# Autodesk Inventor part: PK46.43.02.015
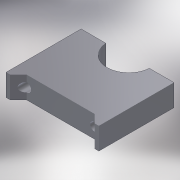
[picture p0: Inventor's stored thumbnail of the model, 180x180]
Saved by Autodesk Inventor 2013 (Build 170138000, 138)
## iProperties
Shininess: 64.0
Length Units: 11269
Angle Units: 11279
Time Units: 11290
Mass Units: 11283
Length Display Precision: 3
Angle Display Precision: 2
Compacted: True
Part Number: PK46.43.02.015
Document SubType Name: Modeling
Created: 2004-12
Material: Сталь высокопрочная низколегированная
Designer: ELarisa
Manufacturer: Standard
Standards Organization: Custom
Density: 7.84 g/cm^3
Density: 0.0
Volumn: 0.0
Area: 0.0
PropertySet Name: Model Information
Control State: 0
Master: False
Checked Out: False
Checked Out Date: 2008-10-09
Last Check In Date: 2008-10-09
Author: ELarisa
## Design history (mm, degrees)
sketch "Эскиз1"
  geometry: L1 (-26.065, -28.063)-(-26.065, 26.937); L2 (41.935, 26.937)-(41.935, -28.063); L3 (7.935, 36.963)-(7.935, -16.079); L4 (41.935, -28.063)-(38.935, -28.063); L5 (-23.065, -28.063)-(-26.065, -28.063); L6 (-26.065, 26.937)-(-8.034, 26.937); L7 (23.904, 26.937)-(41.935, 26.937); L8 (-23.065, -28.063)-(-17.065, -22.063); L9 (-17.065, -22.063)-(32.935, -22.063); L10 (32.935, -22.063)-(38.935, -28.063); A1 r 16 centre (7.935, 27.937) between (-8.034, 26.937) and (23.904, 26.937)
  constraints: 20 end point, 6 parallel, 5 perpendicular, 2 point on circle, 1 centre point, 1 collinear, 1 point on line, 1 vertical, 1 other
  dimensions: "d0" = 55 distance of L1.start L1.end; "d1" = 68 distance of L1.end L2.start; "d2" = 34 distance from line of L1 A1.centre; "d6" = 32 diameter of A1; "d20" = 1 distance from line of L7 A1.centre; "d21" = 55 distance of L2.start L2.end (= d0); "d23" = 6 distance between parallel lines of L9 L5; "d24" = 50 distance of L9.end L8.end; "d25" = 25 distance from line of L3 L8.end (= 0.5 x d24); "d26" = 135 deg angle of L8 L5
extrude "Выдавливание1" new body sketch "Эскиз1" distance "d7" = 16; taper "d8" = 0 deg
sketch "Эскиз2"
  geometry: L1 (-49.969, 0)-(-49.969, -16) reference; L2 (-49.969, -16)-(-31.937, -16) reference; L3 (-31.937, 0)-(-31.937, -16) reference; L4 (-49.969, 0)-(-31.937, 0) reference; 2 further points
  dimensions: "d9" = 50 distance of point (9.031, -8) point (-40.969, -8); "d10" = 8 distance from line of L2 point (-40.969, -8); "d11" = 9 distance from line of L1 point (-40.969, -8); "d12" = 0 vertical distance of point (9.031, -8) point (-40.969, -8)
hole "Отверстие1" sketch "Эскиз2" diameter "d13" = 6.647; stored, may be unused: countersink angle "d17" = 82 deg, drill point angle "d19" = 118 deg; dims "d14" = 20, "d15" = 11.2, "d16" = 2, "d18" = 8
body "Solid1"
other parameters: "d3" = 1, "d5" = 74
